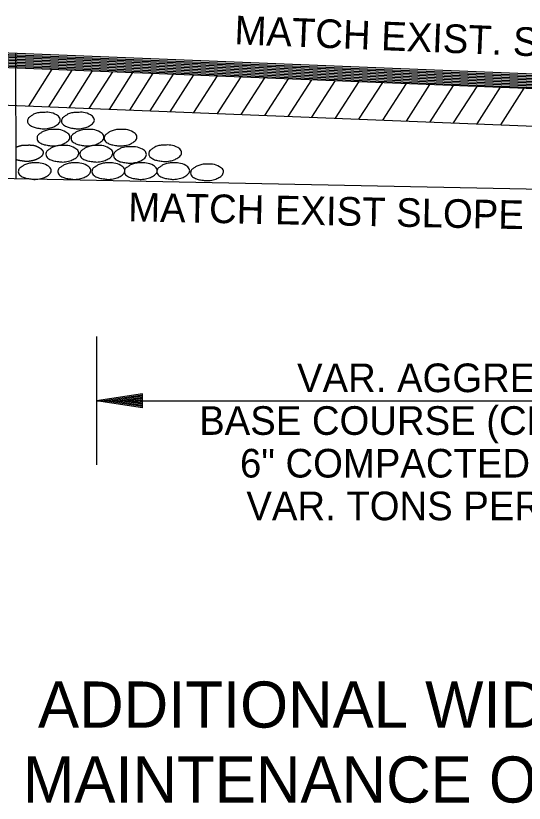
# Model space of a CAD drawing. Extents: x 714919 to 718439, y 1619644 to 1621844.
# Drawn here: x 716813 to 717079.5, y 1620113.2 to 1620525.8 of the extents above; entities that cross this region are included whole.
import ezdxf

# ---------------------------------------------------------------- set-up
doc = ezdxf.new("R2010")
doc.units = 0
doc.layers.add('Default', color=7, linetype='Continuous')

msp = doc.modelspace()

# ---------------------------------------------------------------- linework, layer by layer
at = {"layer": 'Default'}
for p, q in [((716805.01, 1620506.58), (717262.56, 1620488.17)), ((716805.01, 1620505.69), (717263.13, 1620487.27)), ((716805.01, 1620505.03), (717263.49, 1620486.71)), ((716805.01, 1620504.18), (717264.08, 1620485.77)), ((716805.01, 1620503.34), (717264.59, 1620484.98)), ((716812.89, 1620506.28), (716813.06, 1620440.41)), ((716805.01, 1620502.61), (717265.17, 1620484.06)), ((716805.01, 1620501.85), (717265.59, 1620483.4)), ((716805.01, 1620501.08), (717266.17, 1620482.49)), ((716805.01, 1620500.23), (717266.67, 1620481.7)), ((716805.01, 1620499.49), (717267.25, 1620480.78)), ((716805.01, 1620498.82), (717267.59, 1620480.24)), ((716819.82, 1620478.43), (716832.06, 1620497.8)), ((716830.37, 1620478.02), (716842.61, 1620497.35)), ((716840.95, 1620477.59), (716853.21, 1620496.95)), ((716851.56, 1620477.17), (716863.84, 1620496.43)), ((716862.18, 1620476.75), (716874.42, 1620496.08)), ((716872.86, 1620476.33), (716885.01, 1620495.62)), ((716883.42, 1620475.92), (716895.62, 1620495.24)), ((716893.93, 1620475.5), (716906.4, 1620494.74)), ((716906.33, 1620475.01), (716918.76, 1620494.23)), ((716918.72, 1620474.54), (716931.21, 1620493.77)), ((716931.09, 1620474.03), (716943.51, 1620493.31)), ((716943.55, 1620473.53), (716955.94, 1620492.8)), ((716955.84, 1620473.06), (716968.21, 1620492.26)), ((716968.25, 1620472.56), (716980.61, 1620491.8)), ((716980.63, 1620472.08), (716992.98, 1620491.25)), ((716992.88, 1620471.58), (717005.34, 1620490.79)), ((717005.39, 1620471.1), (717017.77, 1620490.35)), ((717017.71, 1620470.61), (717030.04, 1620489.84)), ((717030.12, 1620470.12), (717042.46, 1620489.28)), ((717042.38, 1620469.64), (717054.83, 1620488.77)), ((717054.78, 1620469.15), (717067.13, 1620488.31)), ((717067.23, 1620468.65), (717079.5, 1620487.77)), ((716804.61, 1620479.03), (717280.28, 1620460.25)), ((716665.66, 1620443.36), (717443.68, 1620427.8)), ((716855.28, 1620357.66), (716855.28, 1620290.48)), ((716879.45, 1620327.7), (716855.28, 1620324.07)), ((716879.45, 1620327.09), (716859.31, 1620324.07)), ((716879.45, 1620326.47), (716863.48, 1620324.07)), ((716879.45, 1620325.86), (716867.51, 1620324.07)), ((716879.45, 1620325.26), (716871.59, 1620324.07)), ((716879.45, 1620320.44), (716879.45, 1620327.7)), ((716855.28, 1620324.07), (717262.56, 1620324.07)), ((716879.45, 1620320.44), (716855.28, 1620324.07)), ((716879.45, 1620321.05), (716859.31, 1620324.07)), ((716879.45, 1620321.67), (716863.48, 1620324.07)), ((716879.45, 1620322.28), (716867.51, 1620324.07)), ((716879.45, 1620322.9), (716871.59, 1620324.07)), ((716879.45, 1620324.63), (716875.62, 1620324.07)), ((716879.45, 1620323.51), (716875.62, 1620324.07))]:
    msp.add_line(p, q, dxfattribs=at)
for points in [[(716827.59, 1620475.14), (716830.67, 1620475.12), (716834.34, 1620473.84), (716836.13, 1620472.16), (716836.37, 1620471.08), (716835.45, 1620469.22), (716834.4, 1620468.44), (716832.39, 1620467.39), (716829.44, 1620466.71), (716827.91, 1620466.54), (716825.68, 1620466.77), (716823.14, 1620467.19), (716821.23, 1620467.93), (716819.46, 1620469.4), (716819.15, 1620470.57), (716819.68, 1620472.22), (716821.09, 1620473.29), (716822.38, 1620474.14), (716824.43, 1620474.84), (716825.7, 1620475.12), (716827.59, 1620475.14)], [(716845.43, 1620475.14), (716848.51, 1620475.12), (716852.17, 1620473.84), (716853.97, 1620472.16), (716854.21, 1620471.08), (716853.28, 1620469.22), (716852.23, 1620468.44), (716850.22, 1620467.39), (716847.28, 1620466.71), (716845.75, 1620466.54), (716843.51, 1620466.77), (716840.97, 1620467.19), (716839.06, 1620467.93), (716837.29, 1620469.4), (716836.99, 1620470.57), (716837.51, 1620472.22), (716838.92, 1620473.29), (716840.21, 1620474.14), (716842.26, 1620474.84), (716843.53, 1620475.12), (716845.43, 1620475.14)], [(716832.6, 1620466.16), (716835.69, 1620466.14), (716839.35, 1620464.85), (716841.14, 1620463.18), (716841.39, 1620462.1), (716840.46, 1620460.24), (716839.41, 1620459.46), (716837.4, 1620458.41), (716834.46, 1620457.72), (716832.93, 1620457.56), (716830.69, 1620457.79), (716828.15, 1620458.21), (716826.24, 1620458.95), (716824.47, 1620460.42), (716824.17, 1620461.59), (716824.69, 1620463.24), (716826.1, 1620464.31), (716827.39, 1620465.16), (716829.44, 1620465.86), (716830.71, 1620466.14), (716832.6, 1620466.16)], [(716850.44, 1620466.16), (716853.52, 1620466.14), (716857.19, 1620464.85), (716858.98, 1620463.18), (716859.22, 1620462.1), (716858.29, 1620460.24), (716857.25, 1620459.46), (716855.23, 1620458.41), (716852.29, 1620457.72), (716850.76, 1620457.56), (716848.53, 1620457.79), (716845.99, 1620458.21), (716844.07, 1620458.95), (716842.3, 1620460.42), (716842, 1620461.59), (716842.52, 1620463.24), (716843.93, 1620464.31), (716845.22, 1620465.16), (716847.28, 1620465.86), (716848.55, 1620466.14), (716850.44, 1620466.16)], [(716867.77, 1620466.16), (716870.86, 1620466.14), (716874.52, 1620464.85), (716876.31, 1620463.18), (716876.55, 1620462.1), (716875.63, 1620460.24), (716874.58, 1620459.46), (716872.57, 1620458.41), (716869.63, 1620457.72), (716868.1, 1620457.56), (716865.86, 1620457.79), (716863.32, 1620458.21), (716861.41, 1620458.95), (716859.64, 1620460.42), (716859.34, 1620461.59), (716859.86, 1620463.24), (716861.27, 1620464.31), (716862.56, 1620465.16), (716864.61, 1620465.86), (716865.88, 1620466.14), (716867.77, 1620466.16)], [(716837.27, 1620457.76), (716840.35, 1620457.74), (716844.01, 1620456.45), (716845.81, 1620454.78), (716846.05, 1620453.69), (716845.12, 1620451.84), (716844.07, 1620451.05), (716842.06, 1620450.01), (716839.12, 1620449.32), (716837.59, 1620449.16), (716835.35, 1620449.38), (716832.82, 1620449.8), (716830.9, 1620450.55), (716829.13, 1620452.02), (716828.83, 1620453.19), (716829.35, 1620454.84), (716830.76, 1620455.91), (716832.05, 1620456.75), (716834.1, 1620457.46), (716835.37, 1620457.74), (716837.27, 1620457.76)], [(716855.1, 1620457.76), (716858.18, 1620457.74), (716861.85, 1620456.45), (716863.64, 1620454.78), (716863.88, 1620453.69), (716862.95, 1620451.84), (716861.91, 1620451.05), (716859.89, 1620450.01), (716856.95, 1620449.32), (716855.42, 1620449.16), (716853.19, 1620449.38), (716850.65, 1620449.8), (716848.74, 1620450.55), (716846.96, 1620452.02), (716846.66, 1620453.19), (716847.18, 1620454.84), (716848.59, 1620455.91), (716849.88, 1620456.75), (716851.94, 1620457.46), (716853.21, 1620457.74), (716855.1, 1620457.76)], [(716872.72, 1620457.13), (716875.8, 1620457.11), (716879.47, 1620455.83), (716881.26, 1620454.15), (716881.5, 1620453.07), (716880.58, 1620451.21), (716879.53, 1620450.43), (716877.52, 1620449.38), (716874.58, 1620448.7), (716873.04, 1620448.54), (716870.81, 1620448.76), (716868.27, 1620449.18), (716866.36, 1620449.92), (716864.59, 1620451.39), (716864.28, 1620452.56), (716864.81, 1620454.21), (716866.22, 1620455.28), (716867.51, 1620456.13), (716869.56, 1620456.83), (716870.83, 1620457.11), (716872.72, 1620457.13)], [(716891.17, 1620458.02), (716894.25, 1620458), (716897.91, 1620456.71), (716899.71, 1620455.04), (716899.95, 1620453.95), (716899.02, 1620452.1), (716897.97, 1620451.31), (716895.96, 1620450.26), (716893.02, 1620449.58), (716891.49, 1620449.42), (716889.25, 1620449.64), (716886.71, 1620450.06), (716884.8, 1620450.81), (716883.03, 1620452.28), (716882.73, 1620453.45), (716883.25, 1620455.1), (716884.66, 1620456.17), (716885.95, 1620457.01), (716888, 1620457.72), (716889.27, 1620458), (716891.17, 1620458.02)], [(716822.81, 1620448.64), (716825.89, 1620448.62), (716829.56, 1620447.33), (716831.35, 1620445.66), (716831.59, 1620444.57), (716830.67, 1620442.71), (716829.62, 1620441.93), (716827.6, 1620440.88), (716824.66, 1620440.2), (716823.13, 1620440.04), (716820.9, 1620440.26), (716818.36, 1620440.68), (716816.45, 1620441.43), (716814.67, 1620442.9), (716814.37, 1620444.06), (716814.9, 1620445.72), (716816.31, 1620446.78), (716817.6, 1620447.63), (716819.65, 1620448.33), (716820.92, 1620448.62), (716822.81, 1620448.64)], [(716843.57, 1620448.64), (716846.65, 1620448.62), (716850.32, 1620447.33), (716852.11, 1620445.66), (716852.35, 1620444.57), (716851.42, 1620442.71), (716850.38, 1620441.93), (716848.36, 1620440.88), (716845.42, 1620440.2), (716843.89, 1620440.04), (716841.66, 1620440.26), (716839.12, 1620440.68), (716837.21, 1620441.43), (716835.43, 1620442.9), (716835.13, 1620444.06), (716835.65, 1620445.72), (716837.06, 1620446.78), (716838.35, 1620447.63), (716840.41, 1620448.33), (716841.68, 1620448.62), (716843.57, 1620448.64)], [(716861.4, 1620448.64), (716864.49, 1620448.62), (716868.15, 1620447.33), (716869.94, 1620445.66), (716870.18, 1620444.57), (716869.26, 1620442.71), (716868.21, 1620441.93), (716866.2, 1620440.88), (716863.26, 1620440.2), (716861.73, 1620440.04), (716859.49, 1620440.26), (716856.95, 1620440.68), (716855.04, 1620441.43), (716853.27, 1620442.9), (716852.97, 1620444.06), (716853.49, 1620445.72), (716854.9, 1620446.78), (716856.19, 1620447.63), (716858.24, 1620448.33), (716859.51, 1620448.62), (716861.4, 1620448.64)], [(716878.38, 1620448.64), (716881.46, 1620448.62), (716885.13, 1620447.33), (716886.92, 1620445.66), (716887.16, 1620444.57), (716886.24, 1620442.71), (716885.19, 1620441.93), (716883.18, 1620440.88), (716880.23, 1620440.2), (716878.7, 1620440.04), (716876.47, 1620440.26), (716873.93, 1620440.68), (716872.02, 1620441.43), (716870.25, 1620442.9), (716869.94, 1620444.06), (716870.47, 1620445.72), (716871.88, 1620446.78), (716873.17, 1620447.63), (716875.22, 1620448.33), (716876.49, 1620448.62), (716878.38, 1620448.64)], [(716895.38, 1620448.64), (716898.46, 1620448.62), (716902.13, 1620447.33), (716903.92, 1620445.66), (716904.16, 1620444.57), (716903.23, 1620442.71), (716902.19, 1620441.93), (716900.17, 1620440.88), (716897.23, 1620440.2), (716895.7, 1620440.04), (716893.47, 1620440.26), (716890.93, 1620440.68), (716889.02, 1620441.43), (716887.24, 1620442.9), (716886.94, 1620444.06), (716887.46, 1620445.72), (716888.87, 1620446.78), (716890.16, 1620447.63), (716892.22, 1620448.33), (716893.49, 1620448.62), (716895.38, 1620448.64)], [(716913.1, 1620447.99), (716916.18, 1620447.97), (716919.84, 1620446.68), (716921.64, 1620445.01), (716921.88, 1620443.92), (716920.95, 1620442.07), (716919.9, 1620441.29), (716917.89, 1620440.24), (716914.95, 1620439.55), (716913.42, 1620439.39), (716911.18, 1620439.61), (716908.64, 1620440.04), (716906.73, 1620440.78), (716904.96, 1620442.25), (716904.66, 1620443.42), (716905.18, 1620445.07), (716906.59, 1620446.14), (716907.88, 1620446.99), (716909.93, 1620447.69), (716911.2, 1620447.97), (716913.1, 1620447.99)]]:
    msp.add_spline(points, degree=3, dxfattribs=at)
for points in [[(716813.02, 1620456.8), (716813.14, 1620456.87), (716813.26, 1620456.95), (716813.38, 1620457.01), (716813.7, 1620457.18), (716814.04, 1620457.31), (716814.39, 1620457.42), (716814.56, 1620457.47), (716814.73, 1620457.52), (716814.91, 1620457.57), (716815.08, 1620457.62), (716815.26, 1620457.67), (716815.44, 1620457.72), (716815.54, 1620457.74), (716815.65, 1620457.77), (716815.75, 1620457.8), (716815.85, 1620457.83), (716815.96, 1620457.86), (716816.07, 1620457.88), (716816.17, 1620457.91), (716816.28, 1620457.93), (716816.38, 1620457.95), (716816.49, 1620457.97), (716816.6, 1620457.98), (716816.7, 1620458), (716817.02, 1620458.04), (716817.33, 1620458.06), (716817.65, 1620458.06), (716817.97, 1620458.06), (716818.28, 1620458.05), (716818.6, 1620458.02)], [(716818.6, 1620458.02), (716818.85, 1620458.03), (716819.11, 1620458.05), (716819.37, 1620458.05), (716819.62, 1620458.06), (716819.88, 1620458.07), (716820.14, 1620458.07), (716820.39, 1620458.07), (716820.65, 1620458.06), (716820.91, 1620458.05), (716821.04, 1620458.04), (716821.17, 1620458.04), (716821.29, 1620458.03), (716821.42, 1620458.02), (716821.55, 1620458.01), (716821.68, 1620458), (716822, 1620457.97), (716822.31, 1620457.91), (716822.63, 1620457.84), (716822.94, 1620457.77), (716823.25, 1620457.67), (716823.55, 1620457.56), (716823.85, 1620457.44), (716824.15, 1620457.32), (716824.45, 1620457.18), (716824.6, 1620457.1), (716824.75, 1620457.03), (716824.9, 1620456.95), (716825.05, 1620456.87), (716825.2, 1620456.79), (716825.34, 1620456.71), (716825.53, 1620456.61), (716825.7, 1620456.49), (716825.87, 1620456.38), (716826.04, 1620456.26), (716826.19, 1620456.14), (716826.34, 1620456), (716826.48, 1620455.86), (716826.62, 1620455.71), (716826.75, 1620455.56), (716826.82, 1620455.48), (716826.89, 1620455.39), (716826.95, 1620455.31), (716827.01, 1620455.22), (716827.08, 1620455.13), (716827.14, 1620455.04), (716827.19, 1620454.95), (716827.24, 1620454.86), (716827.28, 1620454.77), (716827.32, 1620454.68), (716827.35, 1620454.59), (716827.37, 1620454.5), (716827.39, 1620454.4), (716827.4, 1620454.31), (716827.4, 1620454.22), (716827.4, 1620454.17), (716827.4, 1620454.13), (716827.4, 1620454.08), (716827.39, 1620454.04), (716827.39, 1620453.99), (716827.38, 1620453.95), (716827.35, 1620453.78), (716827.31, 1620453.62), (716827.26, 1620453.46), (716827.2, 1620453.3), (716827.14, 1620453.14), (716827.07, 1620452.98), (716826.99, 1620452.82), (716826.9, 1620452.67), (716826.8, 1620452.52), (716826.75, 1620452.45), (716826.69, 1620452.38), (716826.64, 1620452.31), (716826.58, 1620452.23), (716826.52, 1620452.16), (716826.45, 1620452.1), (716826.29, 1620451.94), (716826.13, 1620451.79), (716825.95, 1620451.66), (716825.77, 1620451.54), (716825.59, 1620451.42), (716825.4, 1620451.31), (716825.08, 1620451.11), (716824.75, 1620450.92), (716824.42, 1620450.73), (716824.26, 1620450.64), (716824.09, 1620450.56), (716823.92, 1620450.48), (716823.83, 1620450.44), (716823.75, 1620450.4), (716823.66, 1620450.37), (716823.57, 1620450.33), (716823.48, 1620450.3), (716823.39, 1620450.26), (716823.15, 1620450.18), (716822.91, 1620450.1), (716822.67, 1620450.04), (716822.42, 1620449.97), (716822.18, 1620449.91), (716821.93, 1620449.86), (716821.69, 1620449.8), (716821.44, 1620449.75), (716821.2, 1620449.71), (716820.95, 1620449.66), (716820.7, 1620449.62), (716820.45, 1620449.58), (716820.2, 1620449.54), (716819.94, 1620449.5), (716819.68, 1620449.46), (716819.56, 1620449.44), (716819.43, 1620449.43), (716819.3, 1620449.43), (716819.17, 1620449.42), (716819.05, 1620449.41), (716818.92, 1620449.42), (716818.55, 1620449.43), (716818.17, 1620449.46), (716817.8, 1620449.5), (716817.43, 1620449.54), (716817.06, 1620449.59), (716816.68, 1620449.64), (716816.47, 1620449.67), (716816.26, 1620449.7), (716816.05, 1620449.73), (716815.83, 1620449.76), (716815.62, 1620449.79), (716815.41, 1620449.83), (716815.2, 1620449.86), (716814.99, 1620449.9), (716814.78, 1620449.94), (716814.57, 1620449.98), (716814.36, 1620450.02), (716814.15, 1620450.06), (716813.95, 1620450.1), (716813.77, 1620450.15), (716813.58, 1620450.22), (716813.39, 1620450.28), (716813.21, 1620450.35), (716813.03, 1620450.43)]]:
    msp.add_open_spline(points, degree=3, dxfattribs=at)

# ---------------------------------------------------------------- texts
for s, rotation, p in [('MATCH EXIST. SLOPE', 357.7077, (716927.44, 1620510.86)), ('MATCH EXIST SLOPE', 358.8543, (716871.85, 1620418.12))]:
    msp.add_text(s, height=15, rotation=rotation, dxfattribs=at).set_placement(p)
for s, height, p in [('VAR. AGGREGATE ', 15, (716960.44, 1620328.59)), ('BASE COURSE (CLASS 7) ', 15, (716909.13, 1620306.22)), ('6" COMPACTED DEPTH ', 15, (716930.54, 1620283.86)), ('VAR. TONS PER STA.', 15, (716933.88, 1620261.49)), ('ADDITIONAL WIDENING ', 24.168, (716824.67, 1620152.84)), ('FOR MAINTENANCE OF TRAFFIC', 24.168, (716739.58, 1620113.57))]:
    msp.add_text(s, height=height, dxfattribs=at).set_placement(p)

doc.saveas('drawing.dxf')
